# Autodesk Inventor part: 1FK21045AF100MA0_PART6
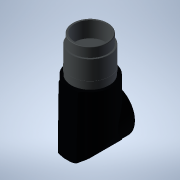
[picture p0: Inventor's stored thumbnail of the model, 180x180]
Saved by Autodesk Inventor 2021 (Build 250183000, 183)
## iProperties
Created: 2025-04
Part Number: 1FK21045AF100MA0_PART6
Material: Generic
Catalog Web Link: www.3dfindit.com
Description: -Servo synchronous motor
Document SubType Name: Modeling
Designer: psAdmin
Mass: 11.0817 g
Surface Area: 35.706 cm^2
Volume: 11.0817 cm^3
Density: 1 g/cm^3
Appearance: PSOLRGB-176-176-176
Category: PARTsolutions
Title: 1FK21045AF100MA0_PART6
Author: Cadenas PARTsolutions
Comments: Servo synchronous motor
Sending System: PARTsolutions
Preprocessor: ST-DEVELOPER v19.3
PSOL_IDENT_0: {$CADENAS_DATA/23d-libs/siemens_ag/_cat_/52/6b/1fk21045af100ma0.prj},213 {VTYP=3D},{NB=1FK21045AF100
PSOL_IDENT_1: MA0_PART6},{LINA=1FK21045AF100MA0_PART6},{NN=1FK21045AF100MA0_PART6},{NOPRJ=TRUE},{DATE=19.08.2025 1
PSOL_IDENT_2: 4:00:38},{GEOMDATE=30.07.2025 02:01:45},{VERSION=},{LINEID=10},{WBVAR=},{WBNUMERIC=}  {NB=1FK21045AF
PSOL_IDENT_3: 100MA0_PART6},{LINA=1FK21045AF100MA0_PART6},{KT=DUMMY},{PREVIEW=../../../_pool_/cb/72/p_d211_xx_0043
PSOL_IDENT_4: 4j.png},{DESCSHORT=SIMOTICS S-1FK2 HD, SINAMICS S210 3AC 400V-480V, 2.4 Nm, 3000 rpm},{DESCLONG=SIMO
PSOL_IDENT_5: TICS S-1FK2 HD servo motor M0=2.4 Nm; PN = 0.75 kW at nN=3000 rpm (380-480 V); PN = 0.375 kW at nN=1
PSOL_IDENT_6: 500 rpm (200-240 V); with holding brake; degree of protection IP64; cylindrical shaft D19x40mm; abso
PSOL_IDENT_7: lute encoder 22-bit + 12-bit multiturn (encoder AM22DQC); with OCC interface; plug size M17, rotatab
PSOL_IDENT_8: le; SIMOTICS S-1FK2 servomotorfor a wide range of uses in industrial environments. SIMOTICS S‑1FK2 s
PSOL_IDENT_9: ervomotors are compact synchronous motors with a high dynamic performance that set themselves apart
PSOL_IDENT_10: as a result of their high power density, degree of protection and overload capability. The motors ar
PSOL_IDENT_11: e available in two variants: as High Dynamic variant (highest dynamic performance as a result of the
PSOL_IDENT_12: low intrinsic moment of inertia for applications demanding a high dynamic performance with low move
PSOL_IDENT_13: d masses) - and as Compact variant (precise and stable closed-loop control for medium up to large mo
PSOL_IDENT_14: ved masses as a result of a medium intrinsic moment of inertia). SIMOTICSS‑1FK2 servomotors fully ex
PSOL_IDENT_15: ploit their strengths in a system with the SINAMICSS210 frequency converter and simple connection us
PSOL_IDENT_16: ing the one cable connection (OCC). Advantages include the short control and positioning times, fast
PSOL_IDENT_17: and precise correction of disturbing quantities as well as stable control with a high dynamic perfo
PSOL_IDENT_18: rmance. The servo motors can be configured to address a wide range of requirements. For example with
PSOL_IDENT_19: and without holding brake, IP64 or IP65 degree of protection, singleturn or multiturn absolute enco
PSOL_IDENT_20: ders - to name just a few. Further, the servomotors are available in different shaft heights extendi
PSOL_IDENT_21: ng from 20 to 100. A shaft sealing ring is available to achieve an IP65 degree of protection and for
PSOL_IDENT_22: subsequent mounting at the motor or as spare part. SIMOTICS - the optimum motor for each and every
PSOL_IDENT_23: motion control application.},{INTNO=804766906411},{SUPPLIERALTNO=1FK2104-5AF10-0MA0},{MANUID=1FK2104
PSOL_IDENT_24: 5AF100MA0},{MANUNAME=Siemens},{MANUTYPEDESC=Synchronous motor 1FK2-HD 2.4 NM},{AAU732=SIMOTICS},{AAO
PSOL_IDENT_25: 057=S-1FK2},{AAU734=SIMOTICS S-1FK2 HD servo motor M0=2.4 Nm; PN = 0.75 kW at nN=3000 rpm (380-480 V
PSOL_IDENT_26: ); PN = 0.375 kW at nN=1500 rpm (200-240 V); with holding brake; degree of protection IP64; cylindri
PSOL_IDENT_27: cal shaft D19x40mm; absolute encoder 22-bit + 12-bit multiturn (encoder AM22DQC); with OCC interface
PSOL_IDENT_28: ; plug size M17, rotatable;},{AAW338=Synchronous motor 1FK2-HD 2.4 NM},{AAO742=SIMOTICS},{AAO663=404
PSOL_IDENT_29: 2948693070},{NOCUPEROU=1},{PRICEQUANTITY=1},{QUANTITYMIN=1},{QUANTITYINT=1},{CTN=85015100},{COO=DE},
PSOL_IDENT_30: {AAO676=1FK2104-5AF10-0MA0},{AAO677=Siemens AG},{ORDERUNIT=C62},{CONTENTUNIT=C62}
NB: 1FK21045AF100MA0_PART6
NT: Servo synchronous motor
NBSYN: $MANUID._PART6
LINA: 1FK21045AF100MA0_PART6
CATALOG: SIEMENS
PREVIEW: ../../../_pool_/cb/72/p_d211_xx_00434j.png
DESCSHORT: SIMOTICS S-1FK2 HD, SINAMICS S210 3AC 400V-480V, 2.4 Nm, 3000 rpm
DESCLONG: SIMOTICS S-1FK2 HD servo motor M0=2.4 Nm; PN = 0.75 kW at nN=3000 rpm (380-480 V); PN = 0.375 kW at nN=1500 rpm (200-240 V); with holding brake; degree of prote
INTNO: 804766906411
SUPPLIERALTNO: 1FK2104-5AF10-0MA0
MANUID: 1FK21045AF100MA0
MANUNAME: Siemens
MANUTYPEDESC: Synchronous motor 1FK2-HD 2.4 NM
AAU732: SIMOTICS
AAO057: S-1FK2
AAU734: SIMOTICS S-1FK2 HD servo motor M0=2.4 Nm; PN = 0.75 kW at nN=3000 rpm (380-480 V); PN = 0.375 kW at nN=1500 rpm (200-240 V); with holding brake; degree of prote
AAW338: Synchronous motor 1FK2-HD 2.4 NM
AAO742: SIMOTICS
AAO663: 4042948693070.0
NOCUPEROU: 1
PRICEQUANTITY: 1
QUANTITYMIN: 1
QUANTITYINT: 1
CTN: 85015100
COO: DE
ARTICLENO: 1FK21045AF100MA0_PART6
BOMINFO: 1FK21045AF100MA0_PART6
CREATOR: CADENAS GmbH
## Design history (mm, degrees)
feature "2025_04_17_15_34_52_0286"
body "Solid1"
